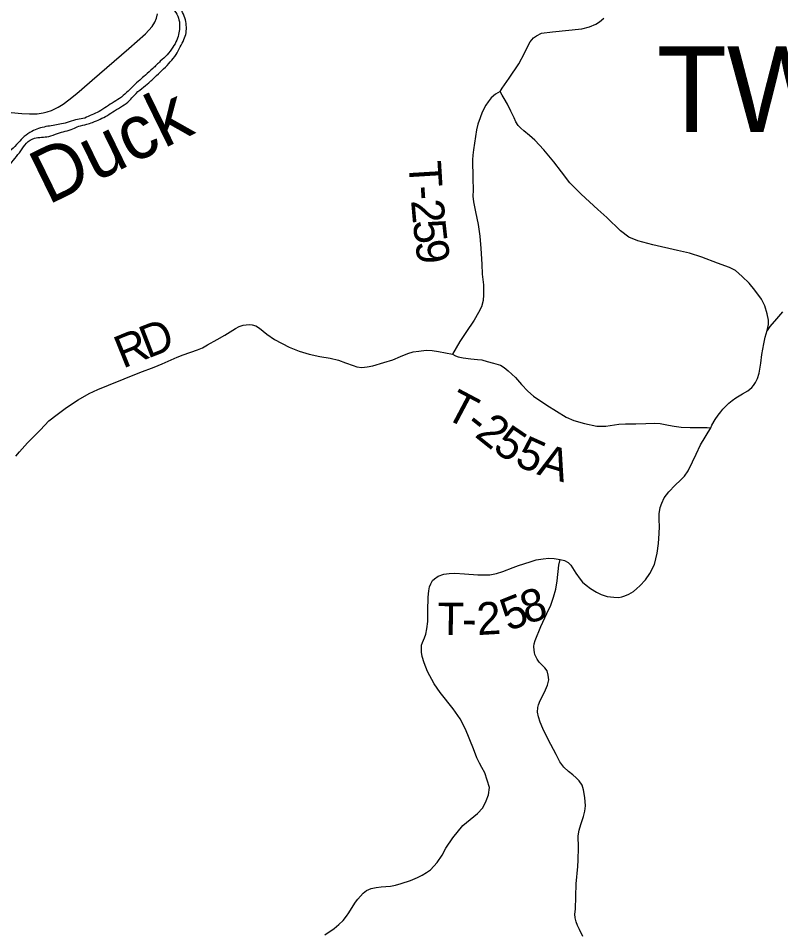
# Model space of a CAD drawing. Extents: x -10.5 to 40.6, y -3.2 to 22.
# Drawn here: x -6.111 to -4.779, y 17.441 to 19.035 of the extents above; entities that cross this region are included whole.
import ezdxf

# ---------------------------------------------------------------- set-up
doc = ezdxf.new("R2010")
doc.units = 0
for name, color, linetype in [('GM_X_County_Road', 7, 'Continuous'), ('GM_X_Major_River', 7, 'Continuous'), ('GM_X_Major_River_Text', 7, 'Continuous'), ('GM_X_State_Route', 7, 'Continuous'), ('GM_X_Township_Road', 7, 'Continuous'), ('GM_X_Township_Road_Text', 7, 'Continuous'), ('GM_X_Township_Text', 7, 'Continuous')]:
    doc.layers.add(name, color=color, linetype=linetype)

msp = doc.modelspace()

# ---------------------------------------------------------------- linework, layer by layer
at = {"layer": 'GM_X_County_Road'}
msp.add_lwpolyline([(-4.7753, 18.5219), (-4.7862, 18.5097), (-4.7978, 18.4966), (-4.8023, 18.4898), (-4.7999, 18.4999), (-4.7999, 18.5078), (-4.8023, 18.5187), (-4.8064, 18.5327), (-4.8122, 18.5442), (-4.824, 18.5601), (-4.8338, 18.5723), (-4.8458, 18.5839), (-4.8577, 18.5943), (-4.8681, 18.5995), (-4.889, 18.6071), (-4.9166, 18.6178), (-4.9382, 18.6245), (-4.959, 18.6295), (-5.0024, 18.6392), (-5.0282, 18.6464), (-5.044, 18.6529), (-5.0587, 18.6637), (-5.0826, 18.6871), (-5.0984, 18.7013), (-5.1275, 18.7277), (-5.147, 18.7477), (-5.162, 18.7671), (-5.175, 18.7842), (-5.1928, 18.805), (-5.2087, 18.8224), (-5.218, 18.8302), (-5.2274, 18.8385), (-5.2326, 18.8432), (-5.2375, 18.8478), (-5.2418, 18.8543), (-5.2447, 18.8611), (-5.2502, 18.873), (-5.256, 18.8851), (-5.2622, 18.8951), (-5.2655, 18.9006), (-5.2688, 18.9071), (-5.2654, 18.9129), (-5.2535, 18.9306), (-5.2363, 18.9554), (-5.2265, 18.9745), (-5.2219, 18.9844), (-5.2167, 18.9943), (-5.2108, 19.0008), (-5.2056, 19.0045), (-5.1965, 19.0091), (-5.1773, 19.0114), (-5.126, 19.0166), (-5.1128, 19.0202), (-5.1017, 19.0251), (-5.0953, 19.0288), (-5.0879, 19.0354)], dxfattribs=at)
at = {"layer": 'GM_X_Major_River'}
for points in [[(-5.8589, 19.0727), (-5.8485, 19.0607), (-5.838, 19.0484), (-5.8313, 19.0356), (-5.8292, 19.0219), (-5.8305, 19.0098), (-5.8341, 18.9972), (-5.8411, 18.9845), (-5.8511, 18.9714), (-5.863, 18.9602), (-5.8761, 18.9474), (-5.8891, 18.9358), (-5.8989, 18.9273), (-5.9104, 18.9168), (-5.922, 18.9052), (-5.934, 18.8952), (-5.9471, 18.887), (-5.9602, 18.8784), (-5.9734, 18.8706), (-5.9858, 18.865), (-5.9982, 18.8599), (-6.0111, 18.8577), (-6.0258, 18.8529), (-6.0386, 18.85), (-6.0503, 18.8479), (-6.0628, 18.8458), (-6.0757, 18.8426), (-6.0873, 18.8374), (-6.1008, 18.8285), (-6.1113, 18.8176), (-6.1236, 18.8053), (-6.1363, 18.7948), (-6.1493, 18.7824), (-6.1613, 18.7739), (-6.1746, 18.7729), (-6.1872, 18.7761), (-6.2009, 18.7781), (-6.2138, 18.7832), (-6.2265, 18.7906), (-6.2391, 18.7961), (-6.2518, 18.8042), (-6.2633, 18.8112), (-6.2755, 18.8163), (-6.2888, 18.818), (-6.2983, 18.8182), (-6.3116, 18.8203), (-6.326, 18.8219), (-6.3405, 18.8247), (-6.3535, 18.829), (-6.3653, 18.8307), (-6.3774, 18.832), (-6.3891, 18.8295), (-6.3989, 18.8248), (-6.4102, 18.8193), (-6.4218, 18.8092), (-6.4303, 18.7973), (-6.4381, 18.7877), (-6.4466, 18.7739), (-6.4517, 18.7605), (-6.4568, 18.7501), (-6.46, 18.7379), (-6.4594, 18.7243), (-6.4565, 18.7118), (-6.4525, 18.6993), (-6.4504, 18.688), (-6.4479, 18.6739), (-6.4458, 18.6603), (-6.441, 18.6471), (-6.4347, 18.6343), (-6.4291, 18.6211), (-6.4247, 18.6083), (-6.4204, 18.5962), (-6.416, 18.5833), (-6.4154, 18.5712), (-6.411, 18.5587), (-6.4058, 18.5467), (-6.3992, 18.5343), (-6.394, 18.5222), (-6.3836, 18.5098), (-6.3712, 18.4987), (-6.3631, 18.4867), (-6.3526, 18.4728), (-6.3482, 18.4603), (-6.3461, 18.4486), (-6.3425, 18.4373), (-6.3434, 18.4232), (-6.3477, 18.4102), (-6.3536, 18.3976), (-6.3632, 18.3856), (-6.3752, 18.3759), (-6.3879, 18.367), (-6.4011, 18.3595), (-6.4135, 18.3525), (-6.4281, 18.3465), (-6.4413, 18.3406), (-6.456, 18.3331), (-6.4692, 18.3291)], [(-6.4358, 18.3297), (-6.423, 18.3352), (-6.4113, 18.3396), (-6.4012, 18.3447), (-6.3895, 18.3502), (-6.376, 18.3569), (-6.3636, 18.3624), (-6.3512, 18.3741), (-6.3427, 18.386), (-6.3346, 18.3987), (-6.3292, 18.4139), (-6.3267, 18.4261), (-6.3254, 18.4387), (-6.3268, 18.4489), (-6.3312, 18.4625), (-6.3374, 18.4738), (-6.3448, 18.4858), (-6.3519, 18.4979), (-6.3619, 18.5072), (-6.3727, 18.5184), (-6.3839, 18.53), (-6.3891, 18.542), (-6.3942, 18.5537), (-6.3978, 18.5662), (-6.4014, 18.5768), (-6.4039, 18.5892), (-6.408, 18.604), (-6.4127, 18.6157), (-6.4183, 18.6289), (-6.4231, 18.6417), (-6.4271, 18.6538), (-6.4303, 18.664), (-6.435, 18.6768), (-6.4371, 18.687), (-6.44, 18.6991), (-6.4417, 18.709), (-6.4434, 18.7211), (-6.4433, 18.7348), (-6.4427, 18.7473), (-6.4388, 18.7596), (-6.4337, 18.7726), (-6.4252, 18.786), (-6.4163, 18.7979), (-6.4051, 18.8084), (-6.3927, 18.8154), (-6.381, 18.8187), (-6.3681, 18.8174), (-6.3562, 18.8134), (-6.3425, 18.8083), (-6.3303, 18.8047), (-6.317, 18.8023), (-6.3067, 18.8017), (-6.2934, 18.8012), (-6.2797, 18.7984), (-6.2695, 18.7971), (-6.2561, 18.7927), (-6.2439, 18.7861), (-6.232, 18.7799), (-6.2205, 18.7728), (-6.2086, 18.7662), (-6.1949, 18.7611), (-6.1812, 18.7572), (-6.1679, 18.7593), (-6.1539, 18.7634), (-6.1407, 18.7678), (-6.1276, 18.7775), (-6.1172, 18.7902), (-6.1065, 18.8037), (-6.0968, 18.8168), (-6.083, 18.8254), (-6.058, 18.8288), (-6.0425, 18.834), (-6.0293, 18.8377), (-6.0157, 18.8421), (-6.0056, 18.8464), (-5.9916, 18.8501), (-5.9814, 18.8533), (-5.9682, 18.8589), (-5.9554, 18.8655), (-5.9431, 18.8734), (-5.9292, 18.882), (-5.9168, 18.8913), (-5.9083, 18.9009), (-5.8952, 18.9125), (-5.8828, 18.9226), (-5.8694, 18.9354), (-5.8571, 18.947), (-5.8455, 18.959), (-5.8355, 18.9717), (-5.8282, 18.9851), (-5.8216, 18.9981), (-5.818, 19.01), (-5.8175, 19.0229), (-5.82, 19.0358), (-5.8255, 19.0486), (-5.8325, 19.0602), (-5.8426, 19.0722)]]:
    msp.add_spline(points, degree=3, dxfattribs=at)
at = {"layer": 'GM_X_State_Route'}
for points in [[(-6, 18.9114), (-5.9819, 18.9269), (-5.918, 18.9821), (-5.8891, 19.0079), (-5.8829, 19.0142), (-5.8772, 19.0209), (-5.8726, 19.0284), (-5.8697, 19.0351), (-5.8677, 19.0427)], [(-6.2151, 18.8795), (-6.1676, 18.875), (-6.1239, 18.8703), (-6.1049, 18.8687), (-6.0917, 18.868), (-6.0781, 18.8683), (-6.0676, 18.8699), (-6.0607, 18.8715), (-6.053, 18.874), (-6.0416, 18.8797), (-6.0326, 18.8851), (-6.0226, 18.8927), (-6.0091, 18.9037), (-6, 18.9114)]]:
    msp.add_lwpolyline(points, dxfattribs=at)
at = {"layer": 'GM_X_Township_Road'}
for points in [[(-5.2688, 18.9071), (-5.2774, 18.9023), (-5.2847, 18.8959), (-5.2899, 18.8893), (-5.294, 18.8833), (-5.3002, 18.8712), (-5.3042, 18.8612), (-5.3078, 18.85), (-5.3105, 18.84), (-5.3157, 18.8053), (-5.317, 18.7959), (-5.3173, 18.7881), (-5.3167, 18.7559), (-5.3164, 18.7349), (-5.3167, 18.7243), (-5.3155, 18.7147), (-5.3121, 18.6967), (-5.3075, 18.6748), (-5.3044, 18.6544), (-5.3027, 18.6326), (-5.3013, 18.6057), (-5.3003, 18.5882), (-5.298, 18.5691), (-5.2979, 18.552), (-5.299, 18.5419), (-5.3019, 18.5307), (-5.3068, 18.5209), (-5.3145, 18.5076), (-5.3288, 18.4863), (-5.3397, 18.4704), (-5.3522, 18.4483)], [(-6.1152, 18.2702), (-6.109, 18.2775), (-6.0952, 18.293), (-6.0722, 18.3157), (-6.0576, 18.3316), (-6.0435, 18.343), (-6.0268, 18.355), (-6.0067, 18.3683), (-5.9874, 18.3794), (-5.9722, 18.3867), (-5.9536, 18.3943), (-5.9264, 18.4049), (-5.8986, 18.4162), (-5.8739, 18.4255), (-5.86, 18.4313), (-5.8335, 18.4429), (-5.8229, 18.4468), (-5.798, 18.4559), (-5.7893, 18.4595), (-5.7806, 18.4644), (-5.7634, 18.4739), (-5.75, 18.4815), (-5.7315, 18.4929), (-5.725, 18.4965), (-5.7182, 18.4989), (-5.7078, 18.5003), (-5.7026, 18.4997), (-5.6963, 18.4976), (-5.6896, 18.4934), (-5.6768, 18.4833), (-5.6632, 18.474), (-5.6376, 18.4603), (-5.6204, 18.4534), (-5.6029, 18.4481), (-5.5839, 18.4441), (-5.5662, 18.441), (-5.5518, 18.4376), (-5.5391, 18.4331), (-5.5262, 18.4281), (-5.5193, 18.4261), (-5.511, 18.4248), (-5.5015, 18.426), (-5.4915, 18.428), (-5.4724, 18.4334), (-5.4568, 18.4385), (-5.4433, 18.4442), (-5.4301, 18.4494), (-5.421, 18.4523), (-5.4112, 18.4536), (-5.3984, 18.4549), (-5.3879, 18.4544), (-5.3769, 18.4528), (-5.3522, 18.4483)], [(-5.1244, 17.4304), (-5.1306, 17.443), (-5.1339, 17.4496), (-5.1363, 17.4563), (-5.1377, 17.4633), (-5.1383, 17.4696), (-5.1374, 17.478), (-5.136, 17.5228), (-5.1333, 17.553), (-5.1325, 17.564), (-5.1323, 17.5863), (-5.1325, 17.6063), (-5.1311, 17.6161), (-5.1281, 17.6265), (-5.1235, 17.6402), (-5.121, 17.6496), (-5.12, 17.6591), (-5.1209, 17.6734), (-5.1232, 17.6866), (-5.1258, 17.695), (-5.131, 17.7023), (-5.1364, 17.7076), (-5.1421, 17.7129), (-5.1494, 17.7187), (-5.1579, 17.7264), (-5.165, 17.736), (-5.1711, 17.7483), (-5.1852, 17.7746), (-5.1943, 17.7941), (-5.199, 17.8052), (-5.2021, 17.8146), (-5.2036, 17.8228), (-5.203, 17.8306), (-5.2018, 17.8353), (-5.1992, 17.8428), (-5.1918, 17.8576), (-5.1863, 17.8696), (-5.1842, 17.879), (-5.1849, 17.8872), (-5.1868, 17.8947), (-5.1907, 17.8999), (-5.1952, 17.9042), (-5.2007, 17.9101), (-5.2045, 17.9153), (-5.2082, 17.9233), (-5.209, 17.9271), (-5.2097, 17.9307), (-5.2101, 17.9375), (-5.2093, 17.9419), (-5.208, 17.948), (-5.1977, 17.9721), (-5.1875, 17.9949), (-5.1806, 18.0098), (-5.1757, 18.0237), (-5.1717, 18.0376), (-5.1693, 18.0519), (-5.1663, 18.0797), (-5.1639, 18.0895), (-5.1568, 18.0877), (-5.15, 18.0841), (-5.1457, 18.0797), (-5.1366, 18.0656), (-5.1292, 18.0549), (-5.1254, 18.0499), (-5.1188, 18.0445), (-5.1114, 18.0388), (-5.1007, 18.0325), (-5.0925, 18.0284), (-5.082, 18.0249), (-5.0705, 18.0234), (-5.0617, 18.0232), (-5.0564, 18.024), (-5.0513, 18.0256), (-5.0439, 18.0285), (-5.0358, 18.0334), (-5.03, 18.0384), (-5.0247, 18.0436), (-5.015, 18.0538), (-5.0072, 18.0646), (-4.9995, 18.0807), (-4.9949, 18.1007), (-4.9923, 18.1173), (-4.9909, 18.135), (-4.9906, 18.1472), (-4.991, 18.1589), (-4.991, 18.1694), (-4.9892, 18.1802), (-4.9867, 18.1876), (-4.9823, 18.1972), (-4.9743, 18.2077), (-4.963, 18.2192), (-4.9539, 18.228), (-4.9467, 18.2351), (-4.9405, 18.2441), (-4.9329, 18.2599), (-4.9267, 18.2736), (-4.919, 18.2896), (-4.9009, 18.3194), (-4.8991, 18.3239), (-4.893, 18.3343), (-4.8883, 18.3415), (-4.8834, 18.3474), (-4.8798, 18.3521), (-4.8756, 18.3563), (-4.8691, 18.3626), (-4.8634, 18.3673), (-4.8573, 18.3716), (-4.8454, 18.3788), (-4.836, 18.3839), (-4.829, 18.3898), (-4.826, 18.3936), (-4.8229, 18.3987), (-4.8192, 18.4058), (-4.8165, 18.4149), (-4.8135, 18.4323), (-4.8117, 18.4478), (-4.8083, 18.4664), (-4.8057, 18.4778), (-4.8023, 18.4898)], [(-5.3522, 18.4483), (-5.3473, 18.445), (-5.3425, 18.4434), (-5.3339, 18.4416), (-5.3203, 18.4398), (-5.3084, 18.4387), (-5.3008, 18.438), (-5.2917, 18.4355), (-5.2804, 18.4325), (-5.2685, 18.4287), (-5.2618, 18.425), (-5.2548, 18.4191), (-5.2424, 18.4074), (-5.2317, 18.3951), (-5.2206, 18.3833), (-5.2106, 18.3749), (-5.1876, 18.3592), (-5.1539, 18.3383), (-5.1405, 18.3325), (-5.1217, 18.3273), (-5.1001, 18.3226), (-5.0844, 18.3226), (-5.0619, 18.3259), (-5.0499, 18.3262), (-5.0319, 18.3266), (-5.0146, 18.3272), (-4.9995, 18.3275), (-4.9895, 18.3271), (-4.9834, 18.3259), (-4.9748, 18.3241), (-4.9647, 18.3221), (-4.9524, 18.3205), (-4.937, 18.3201), (-4.9136, 18.3202), (-4.907, 18.3202), (-4.9009, 18.3194)], [(-5.4065, 17.9396), (-5.4046, 17.9444), (-5.4011, 17.9523), (-5.3988, 17.9591), (-5.397, 17.9682), (-5.3955, 17.981), (-5.3954, 17.9997), (-5.3949, 18.0234), (-5.3938, 18.0345), (-5.3924, 18.0413), (-5.3904, 18.0469), (-5.3871, 18.0525), (-5.3836, 18.0556), (-5.3774, 18.0604), (-5.3676, 18.0636), (-5.358, 18.0649), (-5.3483, 18.0652), (-5.3312, 18.0643), (-5.3081, 18.0623), (-5.2971, 18.0623), (-5.2868, 18.0628), (-5.2757, 18.0651), (-5.2644, 18.0684), (-5.2465, 18.0756), (-5.237, 18.0791), (-5.2163, 18.0855), (-5.2058, 18.0886), (-5.1939, 18.0905), (-5.1837, 18.0916), (-5.1744, 18.0911), (-5.1639, 18.0895)], [(-5.5753, 17.4333), (-5.5593, 17.4446), (-5.5507, 17.4515), (-5.5434, 17.4584), (-5.5378, 17.4659), (-5.5335, 17.472), (-5.5261, 17.484), (-5.5218, 17.4906), (-5.5175, 17.496), (-5.5082, 17.5062), (-5.5025, 17.5109), (-5.4944, 17.5146), (-5.4857, 17.5164), (-5.4767, 17.5171), (-5.4609, 17.5183), (-5.4521, 17.52), (-5.4418, 17.5229), (-5.426, 17.5283), (-5.4135, 17.5337), (-5.4052, 17.5379), (-5.398, 17.5421), (-5.391, 17.5468), (-5.3789, 17.56), (-5.3701, 17.5726), (-5.3637, 17.5846), (-5.352, 17.6031), (-5.3341, 17.6245), (-5.3088, 17.6457), (-5.2995, 17.6556), (-5.2934, 17.6676), (-5.2895, 17.6781), (-5.2877, 17.6909), (-5.2917, 17.7037), (-5.2957, 17.7164), (-5.3011, 17.7256), (-5.3051, 17.7335), (-5.3096, 17.7428), (-5.3156, 17.7585), (-5.3297, 17.7931), (-5.3388, 17.8109), (-5.3512, 17.8285), (-5.3736, 17.8568), (-5.3842, 17.8721), (-5.3959, 17.8935), (-5.4021, 17.9088), (-5.4055, 17.9198), (-5.4064, 17.9277), (-5.4065, 17.9396)]]:
    msp.add_lwpolyline(points, dxfattribs=at)

# ---------------------------------------------------------------- texts
at = {"layer": 'GM_X_Major_River_Text'}
msp.add_text('Duck', height=0.09469, rotation=26.0356, dxfattribs=at).set_placement((-6.0592, 18.7084))
at = {"layer": 'GM_X_Township_Road_Text'}
for s, rotation, p in [('T', 273.482, (-5.4292, 18.7843)), ('-', 273.9888, (-5.4266, 18.7413)), ('2', 275.1301, (-5.4249, 18.7168)), ('5', 276.2203, (-5.4217, 18.6808)), ('9', 277.435, (-5.4177, 18.6447)), ('D', 21.2352, (-5.8853, 18.4401)), ('R', 22.0797, (-5.9284, 18.4226)), ('T', 332.1143, (-5.3688, 18.3384)), ('2', 321.4481, (-5.3152, 18.3053)), ('-', 321.2829, (-5.3336, 18.32)), ('5', 325.7646, (-5.2841, 18.2808)), ('5', 335.7528, (-5.2457, 18.2558)), ('A', 343.1356, (-5.2063, 18.2386)), ('8', 17.594, (-5.2229, 17.9759)), ('5', 21.5601, (-5.2545, 17.9634)), ('T', 359.49, (-5.3786, 17.9574)), ('2', 3.4076, (-5.3085, 17.9571)), ('-', 359.8563, (-5.3357, 17.9571))]:
    msp.add_text(s, height=0.0568, rotation=rotation, dxfattribs=at).set_placement(p)
at = {"layer": 'GM_X_Township_Text'}
msp.add_text('TWP', height=0.15, rotation=0, dxfattribs=at).set_placement((-4.9953, 18.8363))

doc.saveas('drawing.dxf')
